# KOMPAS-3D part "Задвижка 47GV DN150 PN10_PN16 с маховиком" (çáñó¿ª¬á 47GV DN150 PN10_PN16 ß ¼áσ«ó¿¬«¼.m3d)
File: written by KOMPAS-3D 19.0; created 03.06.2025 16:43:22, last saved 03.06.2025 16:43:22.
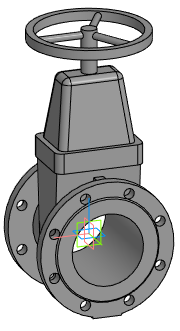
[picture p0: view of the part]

Document properties: Автор: Евгений; Полное имя файла: E:\Dendor Работа Сачек\3D для проекитирвщиков\2.1 Тип 47GV, 47GV.Z Задвижка клиновая фланцевая с обрезиненным клином\stp_Тип 47GV. Задвижка DN40-DN350 с маховиком\Задвижка 47GV DN150 PN10_PN16 с маховиком.m3d

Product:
- Part/product: Задвижка 47GV DN150 PN10_PN16 с маховиком

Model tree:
1. Операция без истории:1  (labels: Задвижка 47GV DN150 PN10_PN16 с маховиком)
